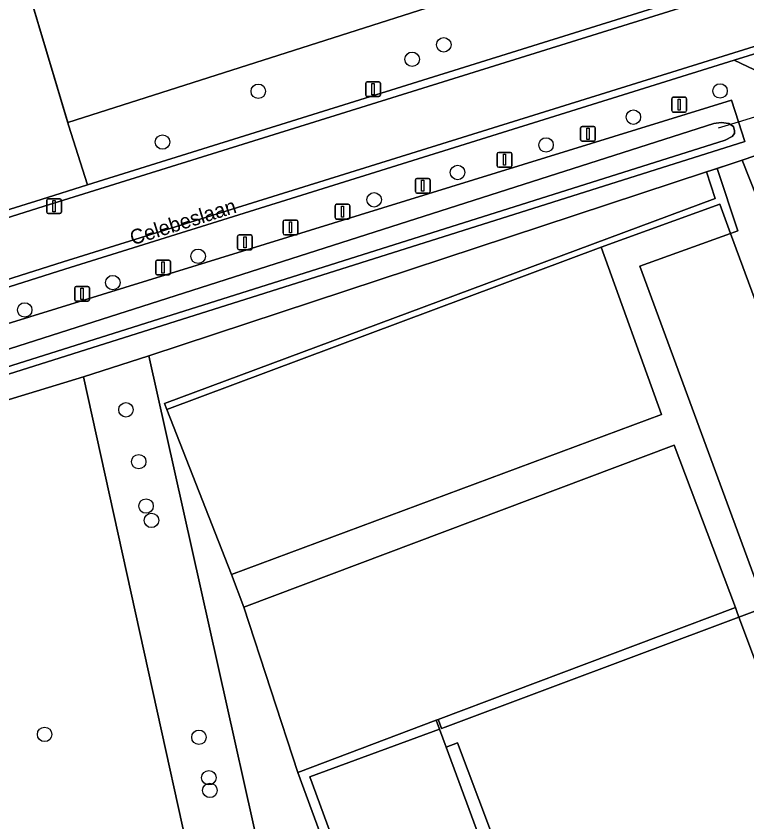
# Model space of a CAD drawing. Extents: x 162879 to 165540, y 384011 to 385181.
# Drawn here: x 163615.5 to 163664.9, y 384429.6 to 384484.1 of the extents above; entities that cross this region are included whole.
import ezdxf

# ---------------------------------------------------------------- set-up
doc = ezdxf.new("R2010")
doc.units = 0
for name, color, linetype in [('IMGEO_Afsluitpaal', 7, 'Continuous'), ('IMGEO_Boom', 7, 'Continuous'), ('IMGEO_Bouwland', 7, 'Continuous'), ('IMGEO_Duiker', 7, 'Continuous'), ('IMGEO_Erf', 7, 'Continuous'), ('IMGEO_Grasland_agrarisch', 7, 'Continuous'), ('IMGEO_Grasland_overig', 7, 'Continuous'), ('IMGEO_Groenvoorziening', 7, 'Continuous'), ('IMGEO_Haag', 7, 'Continuous'), ('IMGEO_Hek', 7, 'Continuous'), ('IMGEO_Lichtmast', 7, 'Continuous'), ('IMGEO_Loofbos', 7, 'Continuous'), ('IMGEO_Oever', 7, 'Continuous'), ('IMGEO_Openbare_ruimte_label', 7, 'Continuous'), ('IMGEO_Pand', 7, 'Continuous'), ('IMGEO_Rijbaan_lokaal_gesloten', 7, 'Continuous'), ('IMGEO_Rijbaan_lokaal_open', 7, 'Continuous'), ('IMGEO_Verkeersbordpaal', 7, 'Continuous'), ('IMGEO_Voetpad_open', 7, 'Continuous'), ('IMGEO_Waterloop', 7, 'Continuous')]:
    doc.layers.add(name, color=color, linetype=linetype)

msp = doc.modelspace()

# ---------------------------------------------------------------- linework, layer by layer
at = {"layer": 'IMGEO_Afsluitpaal'}
for p, q in [((163659.799, 384477.659), (163659.799, 384478.459)), ((163659.799, 384478.459), (163659.799, 384477.659)), ((163659.899, 384478.559), (163660.689, 384478.559)), ((163660.689, 384478.559), (163659.899, 384478.559)), ((163660.789, 384478.459), (163660.789, 384477.659)), ((163660.789, 384477.659), (163660.789, 384478.459)), ((163660.689, 384477.559), (163659.899, 384477.559)), ((163659.899, 384477.559), (163660.689, 384477.559)), ((163653.733, 384476.592), (163654.523, 384476.592)), ((163654.523, 384476.592), (163653.733, 384476.592)), ((163653.633, 384475.692), (163653.633, 384476.492)), ((163653.633, 384476.492), (163653.633, 384475.692)), ((163654.623, 384476.492), (163654.623, 384475.692)), ((163654.623, 384475.692), (163654.623, 384476.492)), ((163654.523, 384475.592), (163653.733, 384475.592)), ((163653.733, 384475.592), (163654.523, 384475.592)), ((163647.998, 384473.937), (163647.998, 384474.737)), ((163647.998, 384474.737), (163647.998, 384473.937)), ((163648.098, 384474.837), (163648.888, 384474.837)), ((163648.888, 384474.837), (163648.098, 384474.837)), ((163648.988, 384474.737), (163648.988, 384473.937)), ((163648.988, 384473.937), (163648.988, 384474.737)), ((163648.888, 384473.837), (163648.098, 384473.837)), ((163648.098, 384473.837), (163648.888, 384473.837)), ((163642.47, 384472.182), (163642.47, 384472.982)), ((163642.47, 384472.982), (163642.47, 384472.182)), ((163642.57, 384473.082), (163643.36, 384473.082)), ((163643.36, 384473.082), (163642.57, 384473.082)), ((163643.46, 384472.982), (163643.46, 384472.182)), ((163643.46, 384472.182), (163643.46, 384472.982)), ((163643.36, 384472.082), (163642.57, 384472.082)), ((163642.57, 384472.082), (163643.36, 384472.082)), ((163637.048, 384470.427), (163637.048, 384471.227)), ((163637.048, 384471.227), (163637.048, 384470.427)), ((163637.148, 384471.327), (163637.938, 384471.327)), ((163637.938, 384471.327), (163637.148, 384471.327)), ((163638.038, 384471.227), (163638.038, 384470.427)), ((163638.038, 384470.427), (163638.038, 384471.227)), ((163633.54, 384469.364), (163633.54, 384470.164)), ((163633.54, 384470.164), (163633.54, 384469.364)), ((163633.64, 384470.264), (163634.43, 384470.264)), ((163634.43, 384470.264), (163633.64, 384470.264)), ((163634.53, 384470.164), (163634.53, 384469.364)), ((163634.53, 384469.364), (163634.53, 384470.164)), ((163637.938, 384470.327), (163637.148, 384470.327)), ((163637.148, 384470.327), (163637.938, 384470.327)), ((163630.457, 384468.353), (163630.457, 384469.153)), ((163630.457, 384469.153), (163630.457, 384468.353)), ((163630.557, 384469.253), (163631.347, 384469.253)), ((163631.347, 384469.253), (163630.557, 384469.253)), ((163631.447, 384469.153), (163631.447, 384468.353)), ((163631.447, 384468.353), (163631.447, 384469.153)), ((163634.43, 384469.264), (163633.64, 384469.264)), ((163633.64, 384469.264), (163634.43, 384469.264)), ((163631.347, 384468.253), (163630.557, 384468.253)), ((163630.557, 384468.253), (163631.347, 384468.253)), ((163624.929, 384466.652), (163624.929, 384467.452)), ((163624.929, 384467.452), (163624.929, 384466.652)), ((163625.029, 384467.552), (163625.819, 384467.552)), ((163625.819, 384467.552), (163625.029, 384467.552)), ((163625.919, 384467.452), (163625.919, 384466.652)), ((163625.919, 384466.652), (163625.919, 384467.452)), ((163625.819, 384466.552), (163625.029, 384466.552)), ((163625.029, 384466.552), (163625.819, 384466.552)), ((163619.556, 384465.772), (163620.346, 384465.772)), ((163620.346, 384465.772), (163619.556, 384465.772)), ((163619.456, 384464.872), (163619.456, 384465.672)), ((163619.456, 384465.672), (163619.456, 384464.872)), ((163620.446, 384465.672), (163620.446, 384464.872)), ((163620.446, 384464.872), (163620.446, 384465.672)), ((163620.346, 384464.772), (163619.556, 384464.772)), ((163619.556, 384464.772), (163620.346, 384464.772))]:
    msp.add_line(p, q, dxfattribs=at)
for points in [[(163660.219, 384478.434), (163660.369, 384478.434), (163660.369, 384477.684), (163660.219, 384477.684), (163660.219, 384478.434)], [(163654.053, 384476.467), (163654.203, 384476.467), (163654.203, 384475.717), (163654.053, 384475.717), (163654.053, 384476.467)], [(163648.418, 384474.712), (163648.568, 384474.712), (163648.568, 384473.962), (163648.418, 384473.962), (163648.418, 384474.712)], [(163642.89, 384472.957), (163643.04, 384472.957), (163643.04, 384472.207), (163642.89, 384472.207), (163642.89, 384472.957)], [(163637.468, 384471.202), (163637.618, 384471.202), (163637.618, 384470.452), (163637.468, 384470.452), (163637.468, 384471.202)], [(163633.96, 384470.139), (163634.11, 384470.139), (163634.11, 384469.389), (163633.96, 384469.389), (163633.96, 384470.139)], [(163630.877, 384469.128), (163631.027, 384469.128), (163631.027, 384468.378), (163630.877, 384468.378), (163630.877, 384469.128)], [(163625.349, 384467.427), (163625.499, 384467.427), (163625.499, 384466.677), (163625.349, 384466.677), (163625.349, 384467.427)], [(163619.876, 384465.647), (163620.026, 384465.647), (163620.026, 384464.897), (163619.876, 384464.897), (163619.876, 384465.647)]]:
    msp.add_lwpolyline(points, dxfattribs=at)
for centre, start, end in [((163659.899, 384478.459), 90, 180), ((163659.899, 384478.459), 90, 180), ((163660.689, 384478.459), 0, 90), ((163660.689, 384478.459), 360, 90), ((163659.899, 384477.659), 180, 270), ((163659.899, 384477.659), 180, 270), ((163660.689, 384477.659), 270, 0), ((163660.689, 384477.659), 270, 0), ((163653.733, 384476.492), 90, 180), ((163653.733, 384476.492), 90, 180), ((163654.523, 384476.492), 0, 90), ((163654.523, 384476.492), 360, 90), ((163653.733, 384475.692), 180, 270), ((163653.733, 384475.692), 180, 270), ((163654.523, 384475.692), 270, 0), ((163654.523, 384475.692), 270, 0), ((163648.098, 384474.737), 90, 180), ((163648.098, 384474.737), 90, 180), ((163648.888, 384474.737), 0, 90), ((163648.888, 384474.737), 360, 90), ((163648.098, 384473.937), 180, 270), ((163648.098, 384473.937), 180, 270), ((163648.888, 384473.937), 270, 0), ((163648.888, 384473.937), 270, 0), ((163642.57, 384472.982), 90, 180), ((163642.57, 384472.982), 90, 180), ((163643.36, 384472.982), 0, 90), ((163643.36, 384472.982), 360, 90), ((163642.57, 384472.182), 180, 270), ((163642.57, 384472.182), 180, 270), ((163643.36, 384472.182), 270, 0), ((163643.36, 384472.182), 270, 0), ((163637.148, 384471.227), 90, 180), ((163637.148, 384471.227), 90, 180), ((163637.938, 384471.227), 0, 90), ((163637.938, 384471.227), 360, 90), ((163633.64, 384470.164), 90, 180), ((163633.64, 384470.164), 90, 180), ((163634.43, 384470.164), 0, 90), ((163634.43, 384470.164), 360, 90), ((163637.148, 384470.427), 180, 270), ((163637.148, 384470.427), 180, 270), ((163637.938, 384470.427), 270, 0), ((163637.938, 384470.427), 270, 0), ((163630.557, 384469.153), 90, 180), ((163630.557, 384469.153), 90, 180), ((163631.347, 384469.153), 0, 90), ((163631.347, 384469.153), 360, 90), ((163633.64, 384469.364), 180, 270), ((163633.64, 384469.364), 180, 270), ((163634.43, 384469.364), 270, 0), ((163634.43, 384469.364), 270, 0), ((163630.557, 384468.353), 180, 270), ((163630.557, 384468.353), 180, 270), ((163631.347, 384468.353), 270, 0), ((163631.347, 384468.353), 270, 0), ((163625.029, 384467.452), 90, 180), ((163625.029, 384467.452), 90, 180), ((163625.819, 384467.452), 0, 90), ((163625.819, 384467.452), 360, 90), ((163625.029, 384466.652), 180, 270), ((163625.029, 384466.652), 180, 270), ((163625.819, 384466.652), 270, 0), ((163625.819, 384466.652), 270, 0), ((163619.556, 384465.672), 90, 180), ((163619.556, 384465.672), 90, 180), ((163620.346, 384465.672), 0, 90), ((163620.346, 384465.672), 360, 90), ((163619.556, 384464.872), 180, 270), ((163619.556, 384464.872), 180, 270), ((163620.346, 384464.872), 270, 0), ((163620.346, 384464.872), 270, 0)]:
    msp.add_arc(centre, 0.1, start, end, dxfattribs=at)
at = {"layer": 'IMGEO_Boom'}
for centre in [(163644.389, 384482.112), (163642.251, 384481.133), (163631.855, 384478.965), (163663.053, 384478.991), (163657.202, 384477.221), (163625.385, 384475.535), (163651.299, 384475.337), (163645.321, 384473.479), (163639.685, 384471.631), (163627.791, 384467.813), (163622.028, 384466.029), (163616.075, 384464.184), (163622.913, 384457.433), (163623.781, 384453.925), (163624.274, 384450.923), (163624.641, 384449.953), (163617.419, 384435.487), (163627.847, 384435.293), (163628.517, 384432.554), (163628.588, 384431.699)]:
    msp.add_circle(centre, 0.489, dxfattribs=at)
at = {"layer": 'IMGEO_Bouwland'}
for points in [[(163630.049, 384446.305), (163659.104, 384457.115), (163655.02, 384468.427), (163625.681, 384457.458)], [(163644.016, 384436.49), (163664.093, 384444.057), (163659.949, 384455.052), (163630.873, 384444.09), (163634.536, 384432.916), (163643.882, 384436.439)]]:
    msp.add_lwpolyline(points, close=True, dxfattribs=at)
at = {"layer": 'IMGEO_Duiker'}
msp.add_lwpolyline([(163662.955, 384476.502), (163664.302, 384476.913), (163667.325, 384477.834), (163672.861, 384479.522), (163675.039, 384480.186), (163677.289, 384480.872)], dxfattribs=at)
at = {"layer": 'IMGEO_Erf'}
msp.add_lwpolyline([(163668.553, 384493.307), (163660.438, 384521.774), (163627.339, 384513.36), (163625.434, 384520.504), (163607.758, 384514.396), (163609.288, 384509.288), (163612.094, 384499.87), (163618.986, 384476.848), (163662.747, 384490.863), (163663.157, 384490.998), (163663.044, 384491.354), (163663.724, 384491.595), (163666.479, 384492.572)], close=True, dxfattribs=at)
at = {"layer": 'IMGEO_Grasland_agrarisch'}
for points in [[(163630.873, 384444.09), (163630.049, 384446.305), (163625.681, 384457.458), (163625.531, 384457.857), (163662.73, 384471.717), (163662.136, 384473.517), (163624.458, 384461.077), (163636.732, 384406.035), (163637.768, 384403.203), (163633.335, 384401.821), (163593.539, 384389.411)], [(163638.715, 384421.511), (163634.536, 384432.916), (163630.873, 384444.09)], [(163672.698, 384421.095), (163664.333, 384443.422), (163644.485, 384435.972), (163644.245, 384435.882), (163644.104, 384436.256), (163644.016, 384436.49), (163643.882, 384436.439), (163644.111, 384435.831), (163644.554, 384434.627), (163645.327, 384434.917), (163648.922, 384425.34)]]:
    msp.add_lwpolyline(points, dxfattribs=at)
msp.add_lwpolyline([(163593.539, 384389.411), (163633.335, 384401.821), (163632.017, 384405.337), (163620.039, 384459.671), (163576.506, 384446.377), (163572.519, 384445.159), (163576.678, 384428.516), (163585.773, 384389.763), (163589.731, 384388.042)], close=True, dxfattribs=at)
at = {"layer": 'IMGEO_Grasland_overig'}
msp.add_lwpolyline([(163664.56, 384474.318), (163662.856, 384473.755), (163664.254, 384469.524), (163663.762, 384469.346), (163672.283, 384446.319), (163673.66, 384442.6), (163676.702, 384443.61)], close=True, dxfattribs=at)
at = {"layer": 'IMGEO_Groenvoorziening'}
for points in [[(163664.558, 384486.47), (163664.413, 384487.033), (163663.157, 384490.998), (163662.747, 384490.863), (163618.986, 384476.848), (163619.034, 384476.687), (163620.324, 384472.642)], [(163665.404, 384474.596), (163664.56, 384474.318), (163676.702, 384443.61), (163677.501, 384443.876)], [(163655.02, 384468.427), (163663.048, 384471.325), (163663.762, 384469.346), (163664.254, 384469.524), (163662.856, 384473.755), (163662.136, 384473.517), (163662.73, 384471.717), (163625.531, 384457.857), (163625.681, 384457.458)], [(163664.333, 384443.422), (163664.192, 384443.796), (163664.093, 384444.057), (163644.016, 384436.49), (163644.104, 384436.256), (163644.245, 384435.882), (163644.485, 384435.972)], [(163644.111, 384435.831), (163643.882, 384436.439), (163634.536, 384432.916), (163638.715, 384421.511), (163648.922, 384425.34), (163645.327, 384434.917), (163644.554, 384434.627), (163647.81, 384425.772), (163639.031, 384422.543), (163635.342, 384432.606)], [(163644.554, 384434.627), (163644.111, 384435.831), (163635.342, 384432.606), (163639.031, 384422.543), (163647.81, 384425.772)]]:
    msp.add_lwpolyline(points, close=True, dxfattribs=at)
for points in [[(163576.506, 384446.377), (163620.039, 384459.671), (163624.458, 384461.077), (163662.136, 384473.517), (163662.856, 384473.755), (163664.56, 384474.318), (163665.404, 384474.596), (163668.063, 384475.474), (163667.325, 384477.834), (163666.715, 384479.784), (163663.998, 384481.064), (163618.797, 384466.945), (163606.62, 384463.084)], [(163611.804, 384462.294), (163663.838, 384478.359), (163664.302, 384476.913), (163664.735, 384475.565), (163612.829, 384459.161)]]:
    msp.add_lwpolyline(points, dxfattribs=at)
at = {"layer": 'IMGEO_Haag'}
for points in [[(163665.404, 384474.596), (163664.56, 384474.318), (163676.702, 384443.61), (163677.501, 384443.876)], [(163664.333, 384443.422), (163664.192, 384443.796), (163664.093, 384444.057), (163644.016, 384436.49), (163644.104, 384436.256), (163644.245, 384435.882), (163644.485, 384435.972)], [(163635.342, 384432.606), (163644.111, 384435.831), (163643.882, 384436.439), (163634.536, 384432.916), (163638.715, 384421.511), (163648.922, 384425.34), (163645.327, 384434.917), (163644.554, 384434.627), (163647.81, 384425.772), (163639.031, 384422.543)]]:
    msp.add_lwpolyline(points, close=True, dxfattribs=at)
at = {"layer": 'IMGEO_Hek'}
for points in [[(163619.034, 384476.687), (163612.094, 384499.87), (163609.288, 384509.288)], [(163620.324, 384472.642), (163619.034, 384476.687)], [(163665.404, 384474.596), (163664.56, 384474.318), (163664.358, 384474.251)], [(163664.358, 384474.251), (163624.458, 384461.077)], [(163624.458, 384461.077), (163620.039, 384459.671)], [(163624.458, 384461.077), (163636.732, 384406.035), (163637.768, 384403.203)], [(163576.506, 384446.377), (163620.039, 384459.671)], [(163620.039, 384459.671), (163632.017, 384405.337), (163633.335, 384401.821)]]:
    msp.add_lwpolyline(points, dxfattribs=at)
at = {"layer": 'IMGEO_Lichtmast'}
for p, q in [((163639.116, 384478.711), (163639.116, 384479.511)), ((163639.116, 384479.511), (163639.116, 384478.711)), ((163639.216, 384479.611), (163640.006, 384479.611)), ((163640.006, 384479.611), (163639.216, 384479.611)), ((163640.106, 384479.511), (163640.106, 384478.711)), ((163640.106, 384478.711), (163640.106, 384479.511)), ((163640.006, 384478.611), (163639.216, 384478.611)), ((163639.216, 384478.611), (163640.006, 384478.611))]:
    msp.add_line(p, q, dxfattribs=at)
msp.add_lwpolyline([(163639.536, 384479.486), (163639.686, 384479.486), (163639.686, 384478.736), (163639.536, 384478.736), (163639.536, 384479.486)], dxfattribs=at)
for centre, start, end in [((163639.216, 384479.511), 90, 180), ((163639.216, 384479.511), 90, 180), ((163640.006, 384479.511), 0, 90), ((163640.006, 384479.511), 360, 90), ((163639.216, 384478.711), 180, 270), ((163639.216, 384478.711), 180, 270), ((163640.006, 384478.711), 270, 0), ((163640.006, 384478.711), 270, 0)]:
    msp.add_arc(centre, 0.1, start, end, dxfattribs=at)
at = {"layer": 'IMGEO_Loofbos'}
msp.add_lwpolyline([(163605.167, 384467.904), (163617.184, 384471.66), (163620.324, 384472.642), (163619.034, 384476.687), (163618.986, 384476.848), (163612.094, 384499.87)], dxfattribs=at)
msp.add_lwpolyline([(163633.335, 384401.821), (163637.768, 384403.203), (163636.732, 384406.035), (163624.458, 384461.077), (163620.039, 384459.671), (163632.017, 384405.337)], close=True, dxfattribs=at)
at = {"layer": 'IMGEO_Oever'}
for points in [[(163572.519, 384445.159), (163572.237, 384446.287), (163612.829, 384459.161), (163664.735, 384475.565), (163664.302, 384476.913), (163663.838, 384478.359), (163611.804, 384462.294), (163588.149, 384454.765), (163570.824, 384448.974), (163570.401, 384448.833), (163561.658, 384445.91), (163560.722, 384445.489)], [(163563.062, 384444.925), (163662.629, 384476.791), (163663.128, 384476.849), (163663.65, 384476.783), (163663.96, 384476.582), (163664.038, 384476.299), (163664.022, 384476.118), (163663.873, 384475.915), (163663.403, 384475.657), (163571.335, 384446.558)]]:
    msp.add_lwpolyline(points, dxfattribs=at)
at = {"layer": 'IMGEO_Pand'}
msp.add_lwpolyline([(163672.283, 384446.319), (163663.762, 384469.346), (163657.643, 384467.137), (163666.137, 384444.092)], close=True, dxfattribs=at)
at = {"layer": 'IMGEO_Rijbaan_lokaal_gesloten'}
msp.add_lwpolyline([(163733.943, 384503.731), (163732.744, 384507.516), (163666.524, 384486.547), (163617.326, 384471.177), (163605.38, 384467.425), (163606.478, 384463.562), (163618.666, 384467.431), (163666.742, 384482.429)], close=True, dxfattribs=at)
at = {"layer": 'IMGEO_Rijbaan_lokaal_open'}
for points in [[(163791.216, 384525.336), (163785.969, 384523.751), (163755.812, 384514.166), (163753.158, 384513.373), (163752.94, 384513.318), (163741.607, 384510.449), (163741.517, 384510.426), (163741.054, 384510.309), (163735.16, 384508.836), (163732.632, 384508.009), (163731.366, 384507.637), (163685.29, 384493.062), (163670.255, 384488.274), (163666.391, 384487.043), (163664.558, 384486.47), (163620.324, 384472.642), (163617.184, 384471.66), (163605.167, 384467.904)], [(163605.38, 384467.425), (163617.326, 384471.177), (163666.524, 384486.547), (163732.744, 384507.516), (163735.282, 384508.322), (163741.21, 384509.831), (163753.419, 384512.911), (163755.965, 384513.688), (163786.222, 384523.282), (163791.418, 384524.876)], [(163780.232, 384517.137), (163757.115, 384509.864), (163755.228, 384509.255), (163751.375, 384508.217), (163736.556, 384504.526), (163736.228, 384504.447), (163733.943, 384503.731), (163666.742, 384482.429), (163618.666, 384467.431), (163606.478, 384463.562)], [(163606.62, 384463.084), (163618.797, 384466.945), (163663.998, 384481.064), (163673.457, 384484.009), (163733.882, 384503.128), (163736.271, 384503.913), (163736.561, 384504.005), (163746.591, 384506.492), (163755.421, 384508.79), (163759.947, 384510.236), (163780.394, 384516.674)]]:
    msp.add_lwpolyline(points, dxfattribs=at)
msp.add_lwpolyline([(163679.03, 384440.096), (163677.501, 384443.876), (163676.702, 384443.61), (163673.66, 384442.6), (163672.283, 384446.319), (163666.137, 384444.092), (163664.333, 384443.422), (163672.698, 384421.095), (163674.291, 384421.776), (163673.315, 384424.399), (163670.04, 384433.203), (163672.621, 384434.163), (163672.163, 384435.238), (163669.34, 384434.179), (163668.569, 384436.044), (163678.316, 384439.819)], close=True, dxfattribs=at)
at = {"layer": 'IMGEO_Verkeersbordpaal'}
for p, q in [((163617.663, 384471.702), (163618.453, 384471.702)), ((163618.453, 384471.702), (163617.663, 384471.702)), ((163617.563, 384470.802), (163617.563, 384471.602)), ((163617.563, 384471.602), (163617.563, 384470.802)), ((163618.553, 384471.602), (163618.553, 384470.802)), ((163618.553, 384470.802), (163618.553, 384471.602)), ((163618.453, 384470.702), (163617.663, 384470.702)), ((163617.663, 384470.702), (163618.453, 384470.702))]:
    msp.add_line(p, q, dxfattribs=at)
msp.add_lwpolyline([(163617.983, 384471.577), (163618.133, 384471.577), (163618.133, 384470.827), (163617.983, 384470.827), (163617.983, 384471.577)], dxfattribs=at)
for centre, start, end in [((163617.663, 384471.602), 90, 180), ((163617.663, 384471.602), 90, 180), ((163618.453, 384471.602), 0, 90), ((163618.453, 384471.602), 360, 90), ((163617.663, 384470.802), 180, 270), ((163617.663, 384470.802), 180, 270), ((163618.453, 384470.802), 270, 0), ((163618.453, 384470.802), 270, 0)]:
    msp.add_arc(centre, 0.1, start, end, dxfattribs=at)
at = {"layer": 'IMGEO_Voetpad_open'}
for points in [[(163672.861, 384479.522), (163672.218, 384481.736), (163673.457, 384484.009), (163663.998, 384481.064), (163666.715, 384479.784), (163667.325, 384477.834), (163668.063, 384475.474), (163668.105, 384475.36), (163668.85, 384475.602), (163672.805, 384476.879), (163673.315, 384477.045), (163673.558, 384477.124), (163673.525, 384477.235)], [(163664.093, 384444.057), (163664.192, 384443.796), (163664.333, 384443.422), (163666.137, 384444.092), (163657.643, 384467.137), (163663.762, 384469.346), (163663.048, 384471.325), (163655.02, 384468.427), (163659.104, 384457.115), (163630.049, 384446.305), (163630.873, 384444.09), (163659.949, 384455.052)]]:
    msp.add_lwpolyline(points, close=True, dxfattribs=at)
at = {"layer": 'IMGEO_Waterloop'}
for points in [[(163663.403, 384475.657), (163663.873, 384475.915), (163664.022, 384476.118), (163664.038, 384476.299), (163663.96, 384476.582), (163663.65, 384476.783), (163663.128, 384476.849), (163662.629, 384476.791), (163563.062, 384444.925)], [(163644.505, 384398.904), (163644.012, 384398.649), (163642.764, 384398.239), (163641.551, 384397.841), (163639.269, 384397.52), (163636.159, 384397.082), (163634.923, 384396.764), (163629.575, 384395.004), (163614.516, 384390.247), (163602.248, 384386.386), (163591.521, 384382.973), (163590.523, 384382.846), (163589.541, 384382.996), (163588.261, 384383.977), (163587.485, 384384.663), (163585.07, 384388.063), (163571.721, 384444.915), (163571.335, 384446.558), (163663.403, 384475.657)]]:
    msp.add_lwpolyline(points, dxfattribs=at)

# ---------------------------------------------------------------- texts
at = {"layer": 'IMGEO_Openbare_ruimte_label'}
msp.add_text('Celebeslaan', height=1, rotation=17.5284, dxfattribs=at).set_placement((163623.371, 384468.548))

doc.saveas('drawing.dxf')
